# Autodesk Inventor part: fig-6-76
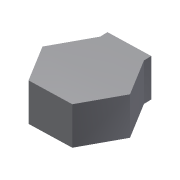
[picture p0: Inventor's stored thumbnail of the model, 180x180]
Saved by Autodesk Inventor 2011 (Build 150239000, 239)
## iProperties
Created: 2009-03
Part Number: fig-6-76
Document SubType Name: Modeling
Designer: Sham
Density: 1 g/cm^3
Author: Sham
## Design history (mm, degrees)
sketch "Sketch5"
  geometry: L1 (-5.929, 9.627)-(5.372, 9.948); L2 (5.372, 9.948)-(11.301, 0.321); L3 (11.301, 0.321)-(5.929, -9.627); L4 (5.929, -9.627)-(-5.372, -9.948); L5 (-5.372, -9.948)-(-11.301, -0.321); L6 (-11.301, -0.321)-(-5.929, 9.627); 1 further point
  constraints: 12 end point, 13 other
extrude "Extrusion3" new body sketch "Sketch5" distance "d13" = 10; taper "d14" = 0 deg
thicken "Thicken2" dims "d15" = 2, "d16" = 2
body "Solid4"
